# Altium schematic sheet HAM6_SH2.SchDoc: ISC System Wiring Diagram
size B; DrawnBy: Filiberto Clara; Engineer: Filiberto Clara; Organization: LIGO Laboratory; Address1: California Institute of Technology; Address2: Massachusetts Institute of Technology; SheetNumber: 27; SheetTotal: 37
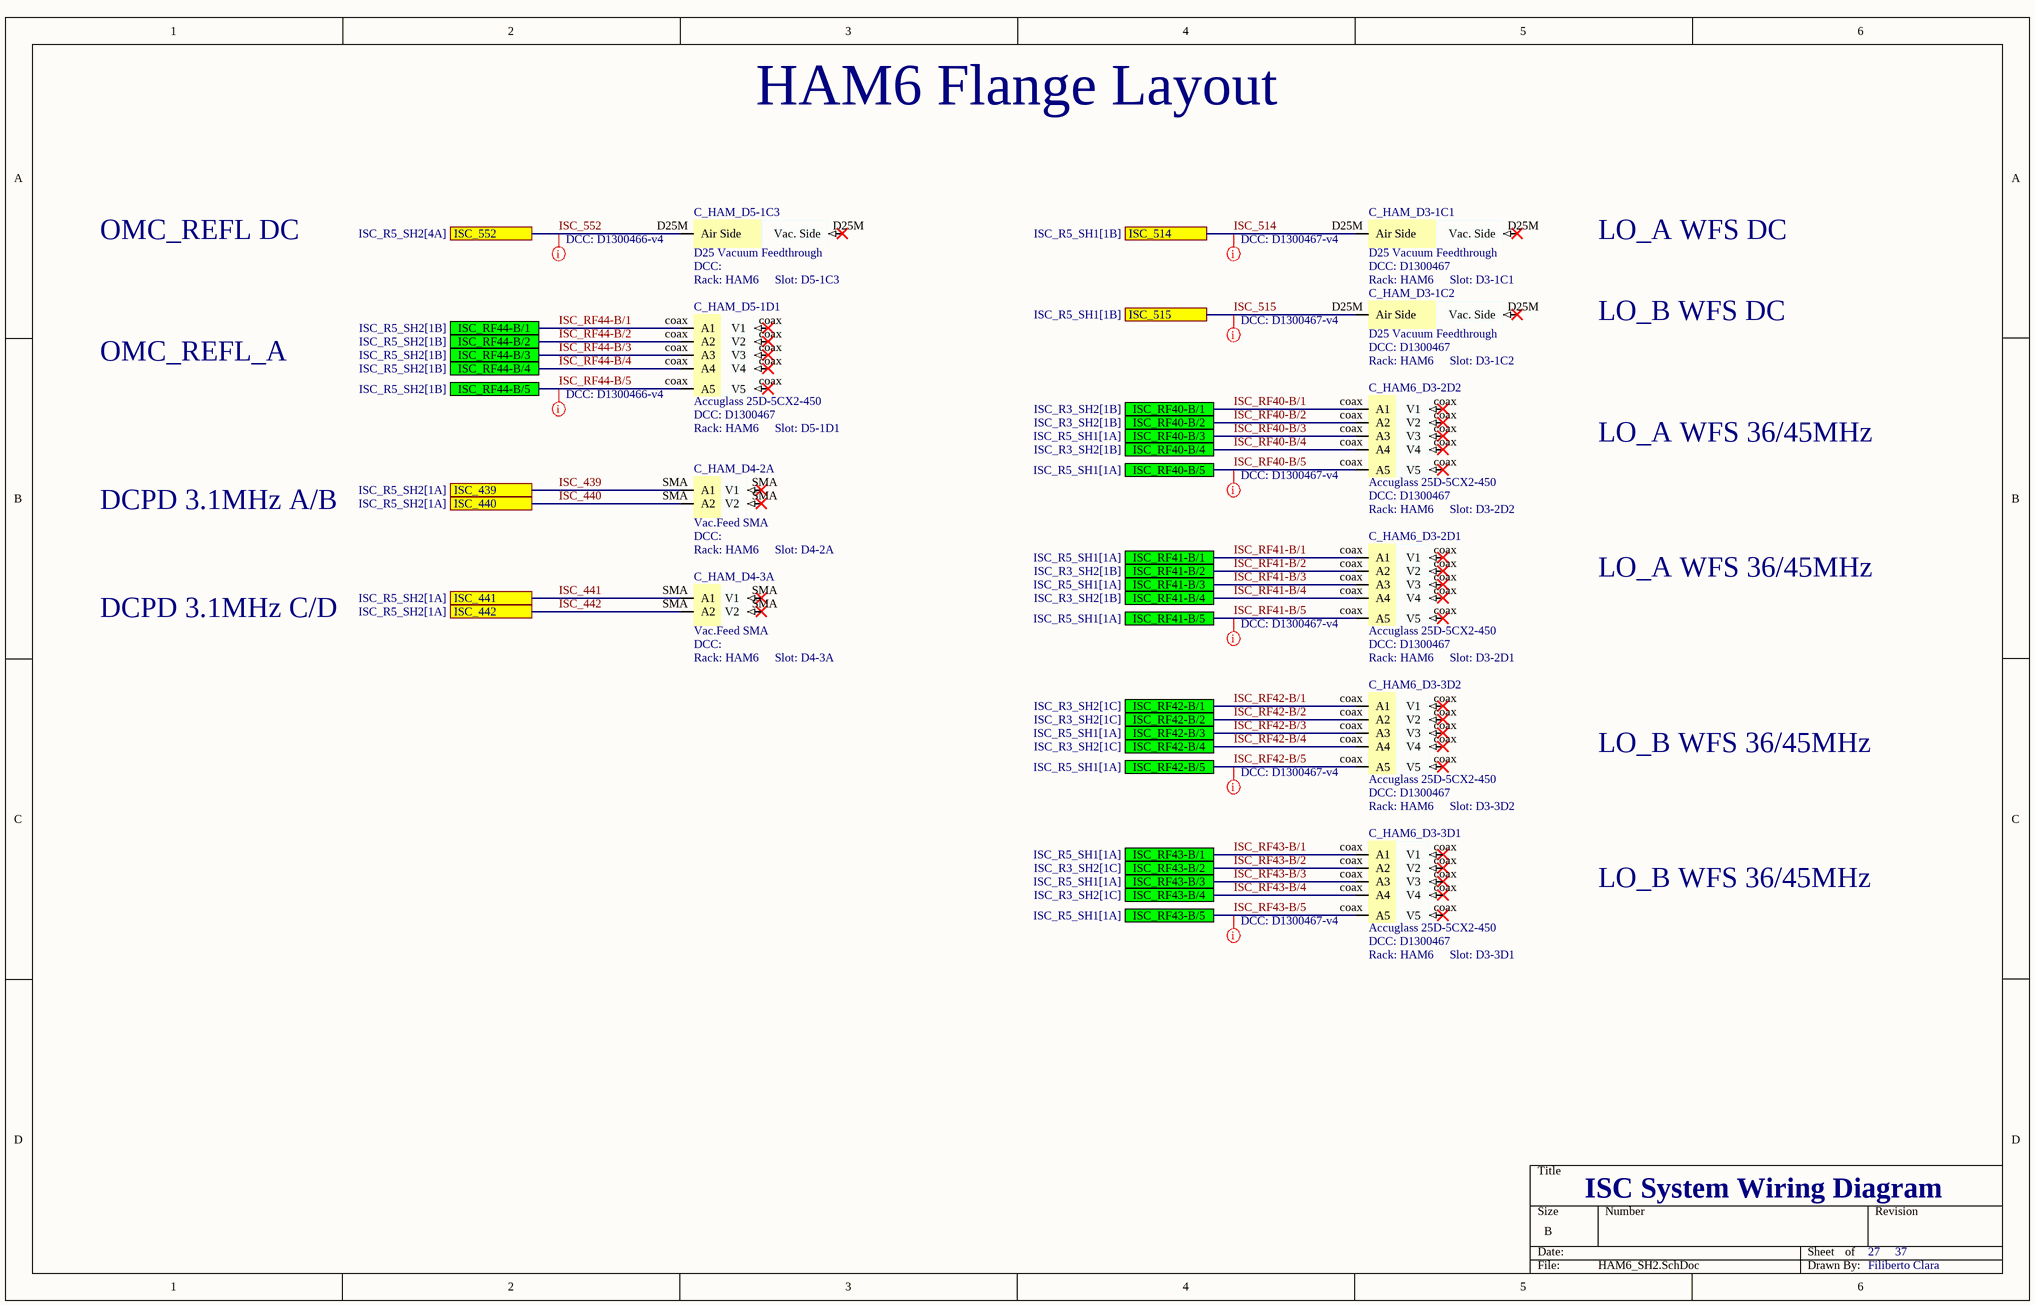
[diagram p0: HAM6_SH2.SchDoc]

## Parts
C_HAM6_D3-2D1  Accuglass 25D-5CX2-450  DCC: D1300467  Rack: HAM6  Slot: D3-2D1
C_HAM6_D3-2D2  Accuglass 25D-5CX2-450  DCC: D1300467  Rack: HAM6  Slot: D3-2D2
C_HAM6_D3-3D1  Accuglass 25D-5CX2-450  DCC: D1300467  Rack: HAM6  Slot: D3-3D1
C_HAM6_D3-3D2  Accuglass 25D-5CX2-450  DCC: D1300467  Rack: HAM6  Slot: D3-3D2
C_HAM_D3-1C1  D25 Vacuum Feedthrough  DCC: D1300467  Rack: HAM6  Slot: D3-1C1
C_HAM_D3-1C2  D25 Vacuum Feedthrough  DCC: D1300467  Rack: HAM6  Slot: D3-1C2
C_HAM_D4-2A  Vac.Feed SMA  Rack: HAM6  Slot: D4-2A
C_HAM_D4-3A  Vac.Feed SMA  Rack: HAM6  Slot: D4-3A
C_HAM_D5-1C3  D25 Vacuum Feedthrough  Rack: HAM6  Slot: D5-1C3
C_HAM_D5-1D1  Accuglass 25D-5CX2-450  DCC: D1300467  Rack: HAM6  Slot: D5-1D1

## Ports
ISC_439 (see ISC_R5_SH2[1A]), ISC_440 (see ISC_R5_SH2[1A]), ISC_441 (see ISC_R5_SH2[1A]), ISC_442 (see ISC_R5_SH2[1A]), ISC_514 (see ISC_R5_SH1[1B]), ISC_515 (see ISC_R5_SH1[1B]), ISC_552 (see ISC_R5_SH2[4A]), ISC_RF40-B/1 (see ISC_R3_SH2[1B]), ISC_RF40-B/2 (see ISC_R3_SH2[1B]), ISC_RF40-B/3 (see ISC_R5_SH1[1A]), ISC_RF40-B/4 (see ISC_R3_SH2[1B]), ISC_RF40-B/5 (see ISC_R5_SH1[1A]), ISC_RF41-B/1 (see ISC_R5_SH1[1A]), ISC_RF41-B/2 (see ISC_R3_SH2[1B]), ISC_RF41-B/3 (see ISC_R5_SH1[1A]), ISC_RF41-B/4 (see ISC_R3_SH2[1B]), ISC_RF41-B/5 (see ISC_R5_SH1[1A]), ISC_RF42-B/1 (see ISC_R3_SH2[1C]), ISC_RF42-B/2 (see ISC_R3_SH2[1C]), ISC_RF42-B/3 (see ISC_R5_SH1[1A]), ISC_RF42-B/4 (see ISC_R3_SH2[1C]), ISC_RF42-B/5 (see ISC_R5_SH1[1A]), ISC_RF43-B/1 (see ISC_R5_SH1[1A]), ISC_RF43-B/2 (see ISC_R3_SH2[1C]), ISC_RF43-B/3 (see ISC_R5_SH1[1A]), ISC_RF43-B/4 (see ISC_R3_SH2[1C]), ISC_RF43-B/5 (see ISC_R5_SH1[1A]), ISC_RF44-B/1 (see ISC_R5_SH2[1B]), ISC_RF44-B/2 (see ISC_R5_SH2[1B]), ISC_RF44-B/3 (see ISC_R5_SH2[1B]), ISC_RF44-B/4 (see ISC_R5_SH2[1B]), ISC_RF44-B/5 (see ISC_R5_SH2[1B])

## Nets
ISC_439: C_HAM_D4-2A.SMA(A1) ; port ISC_439
ISC_440: C_HAM_D4-2A.SMA(A2) ; port ISC_440
ISC_441: C_HAM_D4-3A.SMA(A1) ; port ISC_441
ISC_442: C_HAM_D4-3A.SMA(A2) ; port ISC_442
ISC_514: C_HAM_D3-1C1.D25M(Vac._Side) ; port ISC_514
ISC_515: C_HAM_D3-1C2.D25M(Vac._Side) ; port ISC_515
ISC_552: C_HAM_D5-1C3.D25M(Vac._Side) ; port ISC_552
ISC_RF40-B/1: C_HAM6_D3-2D2.coax(V1) ; port ISC_RF40-B/1
ISC_RF40-B/2: C_HAM6_D3-2D2.coax(A2) ; port ISC_RF40-B/2
ISC_RF40-B/3: C_HAM6_D3-2D2.coax(A3) ; port ISC_RF40-B/3
ISC_RF40-B/4: C_HAM6_D3-2D2.coax(A4) ; port ISC_RF40-B/4
ISC_RF40-B/5: C_HAM6_D3-2D2.coax(A5) ; port ISC_RF40-B/5
ISC_RF41-B/1: C_HAM6_D3-2D1.coax(V1) ; port ISC_RF41-B/1
ISC_RF41-B/2: C_HAM6_D3-2D1.coax(A2) ; port ISC_RF41-B/2
ISC_RF41-B/3: C_HAM6_D3-2D1.coax(A3) ; port ISC_RF41-B/3
ISC_RF41-B/4: C_HAM6_D3-2D1.coax(A4) ; port ISC_RF41-B/4
ISC_RF41-B/5: C_HAM6_D3-2D1.coax(A5) ; port ISC_RF41-B/5
ISC_RF42-B/1: C_HAM6_D3-3D2.coax(V1) ; port ISC_RF42-B/1
ISC_RF42-B/2: C_HAM6_D3-3D2.coax(A2) ; port ISC_RF42-B/2
ISC_RF42-B/3: C_HAM6_D3-3D2.coax(A3) ; port ISC_RF42-B/3
ISC_RF42-B/4: C_HAM6_D3-3D2.coax(A4) ; port ISC_RF42-B/4
ISC_RF42-B/5: C_HAM6_D3-3D2.coax(A5) ; port ISC_RF42-B/5
ISC_RF43-B/1: C_HAM6_D3-3D1.coax(V1) ; port ISC_RF43-B/1
ISC_RF43-B/2: C_HAM6_D3-3D1.coax(A2) ; port ISC_RF43-B/2
ISC_RF43-B/3: C_HAM6_D3-3D1.coax(A3) ; port ISC_RF43-B/3
ISC_RF43-B/4: C_HAM6_D3-3D1.coax(A4) ; port ISC_RF43-B/4
ISC_RF43-B/5: C_HAM6_D3-3D1.coax(A5) ; port ISC_RF43-B/5
ISC_RF44-B/1: C_HAM_D5-1D1.coax(V1) ; port ISC_RF44-B/1
ISC_RF44-B/2: C_HAM_D5-1D1.coax(A2) ; port ISC_RF44-B/2
ISC_RF44-B/3: C_HAM_D5-1D1.coax(A3) ; port ISC_RF44-B/3
ISC_RF44-B/4: C_HAM_D5-1D1.coax(A4) ; port ISC_RF44-B/4
ISC_RF44-B/5: C_HAM_D5-1D1.coax(A5) ; port ISC_RF44-B/5

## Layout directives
DCC: D1300467-v4: ISC_514, ISC_515, ISC_RF40-B/5, ISC_RF41-B/5, ISC_RF42-B/5, ISC_RF43-B/5
DCC: D1300466-v4: ISC_552, ISC_RF44-B/5

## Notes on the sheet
- HAM6 Flange Layout
- OMC_REFL DC
- LO_A WFS DC
- OMC_REFL_A
- LO_B WFS DC
- LO_A WFS 36/45MHz
- DCPD 3.1MHz A/B
- DCPD 3.1MHz C/D
- LO_B WFS 36/45MHz

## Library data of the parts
C_HAM6_D3-2D1 C_HAM6_D3-2D2 C_HAM6_D3-3D1 C_HAM6_D3-3D2 C_HAM_D5-1D1 = Vac.Feed Coax DB 5W5: Vac.Feed Coax Dsub DB5W5; System: ISC
C_HAM_D3-1C1 C_HAM_D3-1C2 C_HAM_D5-1C3 = VacFeedD25: Serial: Sxxxxxxx; System: ISC
C_HAM_D4-2A C_HAM_D4-3A = Vac.Feed SMA: Vac.Feed coax SMA; Serial: Sxxxxxxx; System: ISC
